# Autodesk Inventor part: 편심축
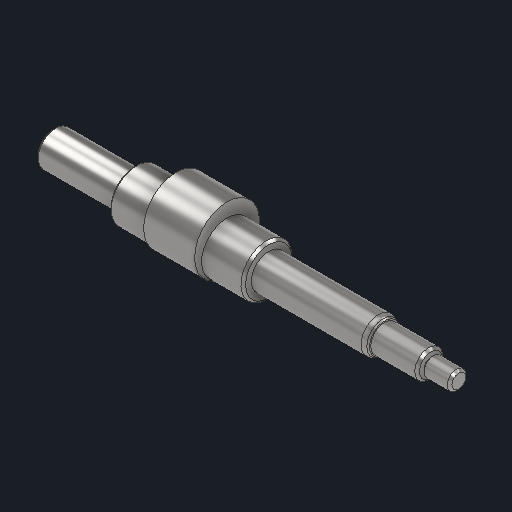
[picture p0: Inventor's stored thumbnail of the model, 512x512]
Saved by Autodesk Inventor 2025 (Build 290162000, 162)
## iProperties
Created: 2025-08
Part Number: 편심축
Material: 강철, 연강
Document SubType Name: Modeling
Designer: infra10
Density: 7.86 g/cm^3
Appearance: 기본값
Author: jhkim
Sending System: Autodesk Inventor 2026
Preprocessor: ST-DEVELOPER v20.1
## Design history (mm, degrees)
feature "솔리드1"
node "솔리드2"
